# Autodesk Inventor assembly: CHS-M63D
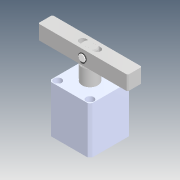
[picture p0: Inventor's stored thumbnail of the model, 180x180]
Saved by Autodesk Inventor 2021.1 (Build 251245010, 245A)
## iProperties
Created: 2019-12
Part Number: CHS-M63D
Description: STEP AP214
Document SubType Name: Assembly
Designer: user
Title: CHS-M63D.STEP
Revision Number: ÈÎºÎ
Sending System: SolidWorks 2016
Preprocessor: SwSTEP 2.0
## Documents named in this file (6)
- D:\Vault_2016\Projekty\Clamptek\Hydraulic\CHS\CHS-63\Inventor\CHS-M63D\CHS-M63D.iam
- D:\Vault_2016\Projekty\Clamptek\Hydraulic\CHS\CHS-63\Inventor\CHS-M63D\CHS-M63(BT).ipt
- D:\Vault_2016\Projekty\Clamptek\Hydraulic\CHS\CHS-63\Inventor\CHS-M63D\CHS-63D»îÈû¸Ë.ipt
- D:\Vault_2016\Projekty\Clamptek\Hydraulic\CHS\CHS-63\Inventor\CHS-M63D\CHS-63D-01_4.ipt
- D:\Vault_2016\Projekty\Clamptek\Hydraulic\CHS\CHS-63\Inventor\CHS-M63D\¶ÌÏú.ipt
- D:\Vault_2016\Projekty\Clamptek\Hydraulic\CHS\CHS-63\Inventor\CHS-M63D\¿¨»É.ipt
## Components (6 placed, 6 different names)
1. CHS-M63(BT)_1
2. CHS-63D»îÈû¸Ë_2
3. CHS-63D-01_4_3
4. ¶ÌÏú_4
5. ¿¨»É_5
6. ¿¨»É_6
